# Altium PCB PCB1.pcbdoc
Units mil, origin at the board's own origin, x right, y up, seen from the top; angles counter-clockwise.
Board outline 3975 x 3427.1 mil, 2 copper layers (Top Layer, Bottom Layer), stack 62.2 mil thick; 7 components, 8 nets, 63 pads, 0 vias.
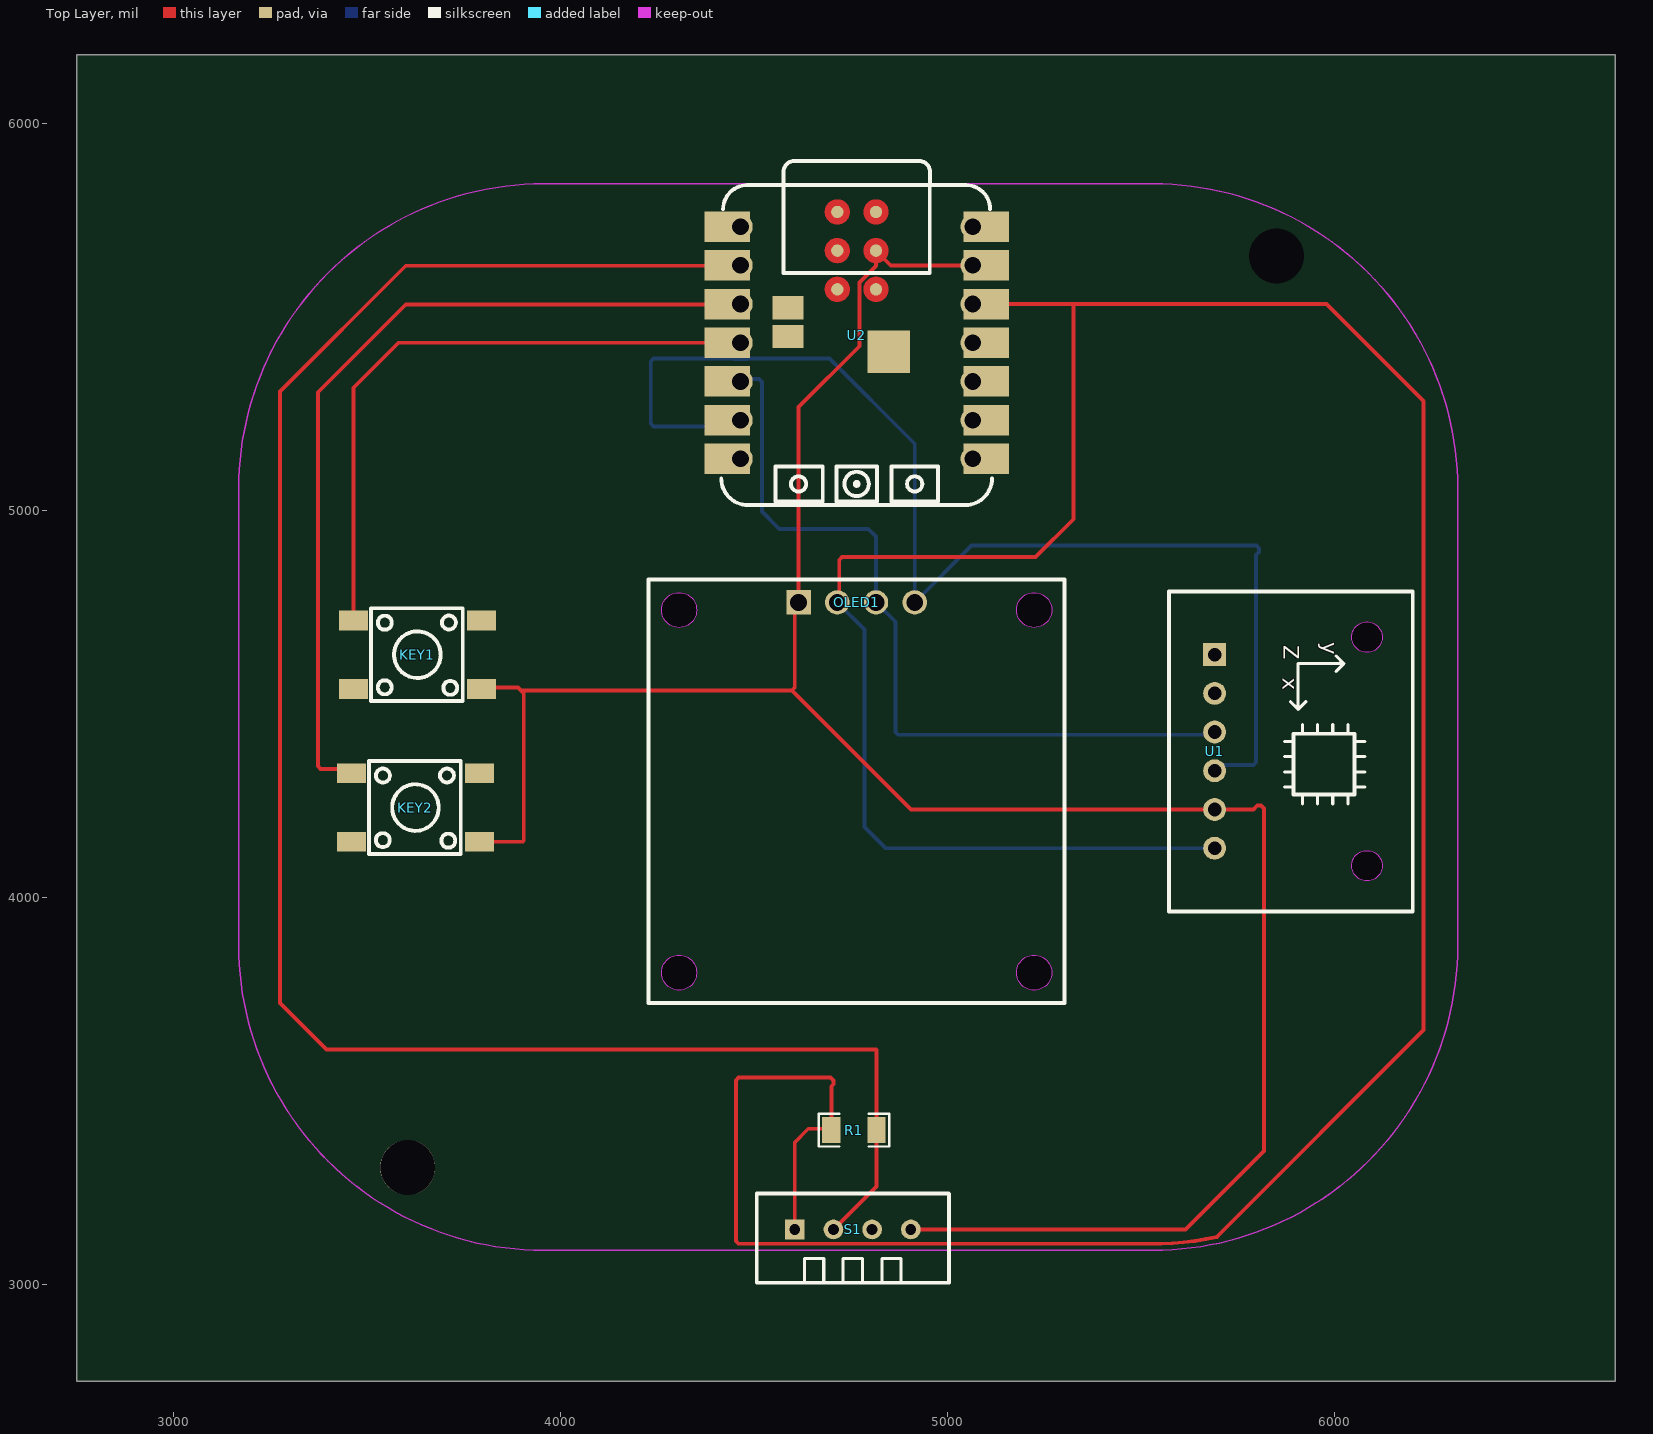
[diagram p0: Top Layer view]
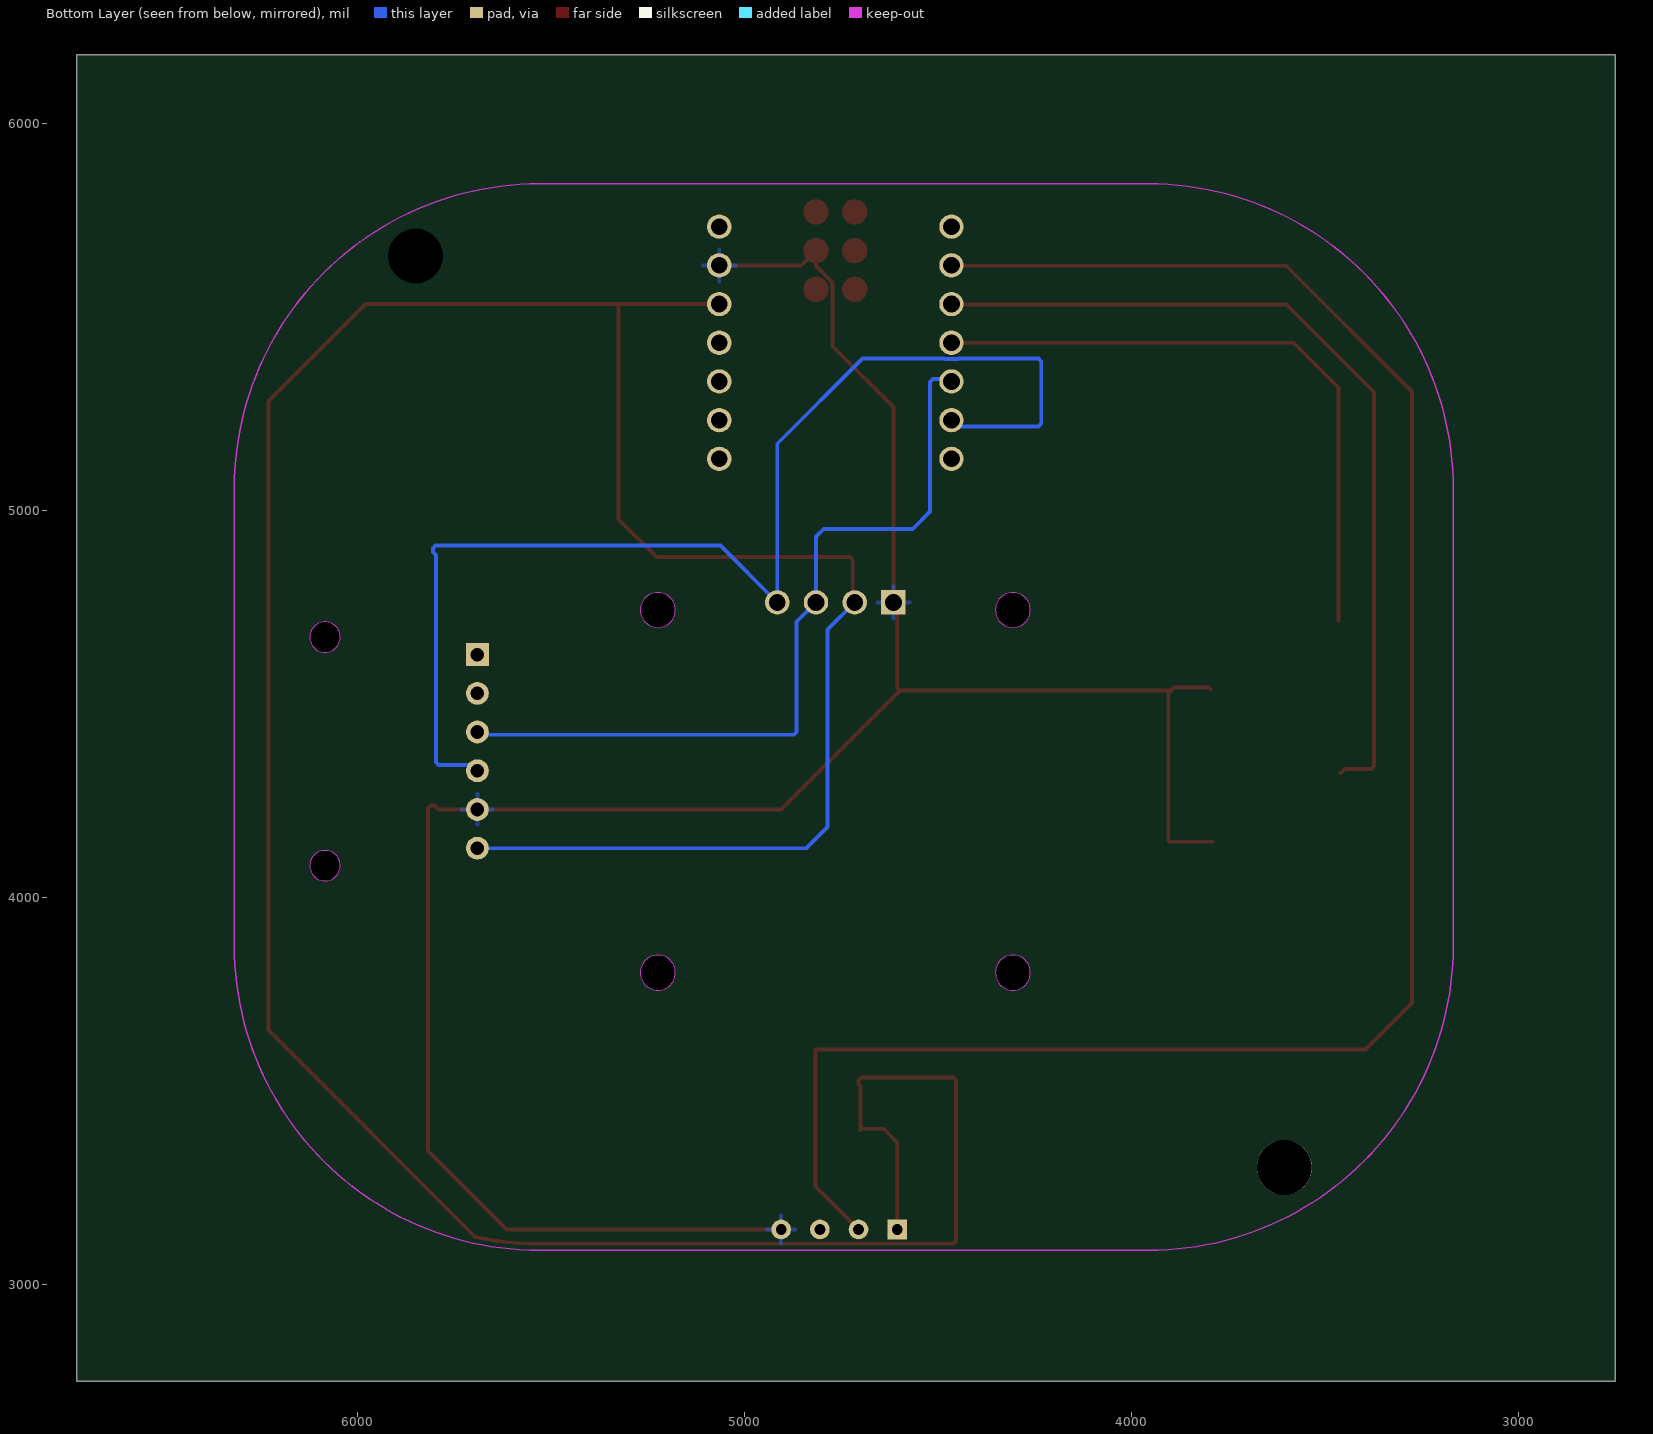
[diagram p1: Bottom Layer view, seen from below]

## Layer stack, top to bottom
Top Solder Mask Layer: solder mask 0.4, Dk 3.3
Top Layer: signal copper 1.4
Dielectric1: surface 59.4, FR4, Dk 4.5
Bottom Layer: signal copper 1.4
Bottom Solder Mask Layer: solder mask 0.4, Dk 3.3

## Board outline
6725,2750 2750,2750 2750,6177.1 6725,6177.1

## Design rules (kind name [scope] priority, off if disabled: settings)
BoardOutlineClearance copperThickness1oz [All] p0: genericclearance=10 ignorepadtopadclearanceinfootprint=FALSE except(0: Arc-SplitContinuation Track-SplitContinuation SMDPad-SplitContinuation THPad-SplitContinuation Via-SplitContinuation Fill-SplitContinuation Poly-SplitContinuation Region-SplitContinuation Text-SplitContinuation)
BoardOutlineClearance copperThickness2oz [All] p0: genericclearance=10 ignorepadtopadclearanceinfootprint=FALSE except(0: Arc-SplitContinuation Track-SplitContinuation SMDPad-SplitContinuation THPad-SplitContinuation Via-SplitContinuation Fill-SplitContinuation Poly-SplitContinuation Region-SplitContinuation Text-SplitContinuation)
BoardOutlineClearance otherClearance [All] p0: genericclearance=10 ignorepadtopadclearanceinfootprint=FALSE except(0: Arc-SplitContinuation Track-SplitContinuation SMDPad-SplitContinuation THPad-SplitContinuation Via-SplitContinuation Fill-SplitContinuation Poly-SplitContinuation Region-SplitContinuation Text-SplitContinuation)
Clearance copperThickness1oz [All] p1: gap=7 ignorepadtopadclearanceinfootprint=FALSE
Clearance copperThickness2oz [All] p1: gap=7 ignorepadtopadclearanceinfootprint=FALSE
Clearance otherClearance [All] p1: gap=7 ignorepadtopadclearanceinfootprint=FALSE
DiffPairsRouting differentialPair [All] p1: maxuncoupledlength=10 minlimit=6 maxlimit=Infinity mostfreqgap=6 toplayer_minwidth=5 toplayer_prefwidth=10 toplayer_maxwidth=100 bottomlayer_minwidth=5 bottomlayer_prefwidth=10 bottomlayer_maxwidth=100
PasteMaskExpansion pasteMaskExpansion [All] p1: expansion=0
PlaneConnect innerPlane [All] p1: planeconnectstyle=Relief reliefexpansion=20 reliefentries=4 reliefconductorwidth=10 reliefairgap=10
PolygonConnect copperRegion [All] p1: connectstyle=Relief reliefentries=4 reliefconductorwidth=10 polygonreliefangle="90 Angle" airgapwidth=10
RoutingVias viaSize [All] p1: viastyle="Through Hole" holewidth=12.0078 minholewidth=11.811 maxholewidth=248.0314 width=12.0078 minwidth=11.811 maxwidth=248.0314
SolderMaskExpansion solderMaskExpansion [IsVia] p1: useseparateexpansions=TRUE expansion=-1000 expansionbottom=-1000
SolderMaskExpansion solderMaskExpansion [All] p2: useseparateexpansions=TRUE expansion=2 expansionbottom=2
Width copperThickness1oz [All] p1: maxlimit=100 minlimit=5 preferedwidth=10
Width copperThickness2oz [All] p1: maxlimit=100 minlimit=8 preferedwidth=10

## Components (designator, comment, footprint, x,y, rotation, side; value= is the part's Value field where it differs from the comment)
KEY1 "BUTTON1" KEY-SMD_4P-L6.0-W6.0-P4.50-LS9.0 3630,4627.1 r0 top
KEY2 "BUTTON1" KEY-SMD_4P-L6.0-W6.0-P4.50-LS9.0 3625,4232.1 r0 top
OLED1 "MC096GW" OLED-TH_4P-L27.8-W27.3_MC096GW 4765,4762.1 r0 top
R1 "10kΩ" R1206 4758,3398.7 r0 top
S1 "DHT11" SENSOR-TH_DHT11-1 4755,3142.1 r0 top
U1 "MPU6050-TH" COMM-TH_MPU6050-TH 5690,4377.1 r270 top
U2 "XIAO ESP32C3" CONN-SMD_XIAO_ESP32C3 4765,5452.1 r0 top

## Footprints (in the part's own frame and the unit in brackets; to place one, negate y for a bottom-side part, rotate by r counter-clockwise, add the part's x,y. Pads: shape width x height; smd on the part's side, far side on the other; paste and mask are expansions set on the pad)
COMM-TH_MPU6050-TH [mil]
  rect 59.1x59.1 hole 35.4 paste+0 mask+2: 1(-250,0)
  round 59.1 hole 35.4 paste+0 mask+2: 2(-150,0) 3(-50,0) 4(50,0) 5(150,0) 6(250,0)
  Board Outline Layer lines w0.1: 296.6,354.4 302.1,354.9 307.4,356.3 312.5,358.3 317.3,361.1 321.6,364.4 325.4,368.4 328.6,372.8 331.2,377.7 333.1,382.9 334.2,388.2 334.6,393.7 334.2,399.2 333.1,404.6 331.2,409.7 328.6,414.6 325.4,419 321.6,423 317.3,426.3 312.5,429.1 307.4,431.1 302.1,432.5 296.6,433 291.1,432.9 285.7,431.9 280.5,430.2 275.6,427.8 271,424.7 266.9,421.1 263.4,416.8 260.5,412.2 258.2,407.2 256.7,401.9 256,396.4 256,391 256.7,385.5 258.2,380.2 260.5,375.2 263.4,370.6 266.9,366.4 271,362.7 275.6,359.6 280.5,357.2 285.7,355.5 291.1,354.5 296.6,354.4 ; -293.9,354.4 -288.5,354.9 -283.1,356.3 -278,358.3 -273.3,361.1 -269,364.4 -265.1,368.4 -261.9,372.8 -259.3,377.7 -257.5,382.9 -256.3,388.2 -255.9,393.7 -256.3,399.2 -257.5,404.6 -259.3,409.7 -261.9,414.6 -265.1,419 -269,423 -273.3,426.3 -278,429.1 -283.1,431.1 -288.5,432.5 -293.9,433 -299.4,432.9 -304.8,431.9 -310.1,430.2 -315,427.8 -319.5,424.7 -323.6,421.1 -327.2,416.8 -330.1,412.2 -332.3,407.2 -333.8,401.9 -334.6,396.4 -334.6,391 -333.8,385.5 -332.3,380.2 -330.1,375.2 -327.2,370.6 -323.6,366.4 -319.5,362.7 -315,359.6 -310.1,357.2 -304.8,355.5 -299.4,354.5 -293.9,354.4
  Board Outline Layer region: -255.9,393.7 -256.3,388.2 -257.5,382.9 -259.3,377.7 -261.9,372.8 -265.1,368.4 -269,364.4 -273.3,361.1 -278,358.3 -283.1,356.3 -288.5,354.9 -293.9,354.4 -299.4,354.5 -304.8,355.5 -310.1,357.2 -315,359.6 -319.5,362.7 -323.6,366.4 -327.2,370.6 -330.1,375.2 -332.3,380.2 -333.8,385.5 -334.6,391 -334.6,396.4 -333.8,401.9 -332.3,407.2 -330.1,412.2 -327.2,416.8 -323.6,421.1 -319.5,424.7 -315,427.8 -310.1,430.2 -304.8,431.9 -299.4,432.9 -293.9,433 -288.5,432.5 -283.1,431.1 -278,429.1 -273.3,426.3 -269,423 -265.1,419 -261.9,414.6 -259.3,409.7 -257.5,404.6 -256.3,399.2
  Board Outline Layer region: -255.9,393.7 -256.3,388.2 -257.5,382.9 -259.3,377.7 -261.9,372.8 -265.1,368.4 -269,364.4 -273.3,361.1 -278,358.3 -283.1,356.3 -288.5,354.9 -293.9,354.4 -299.4,354.5 -304.8,355.5 -310.1,357.2 -315,359.6 -319.5,362.7 -323.6,366.4 -327.2,370.6 -330.1,375.2 -332.3,380.2 -333.8,385.5 -334.6,391 -334.6,396.4 -333.8,401.9 -332.3,407.2 -330.1,412.2 -327.2,416.8 -323.6,421.1 -319.5,424.7 -315,427.8 -310.1,430.2 -304.8,431.9 -299.4,432.9 -293.9,433 -288.5,432.5 -283.1,431.1 -278,429.1 -273.3,426.3 -269,423 -265.1,419 -261.9,414.6 -259.3,409.7 -257.5,404.6 -256.3,399.2
  Board Outline Layer region: 334.6,393.7 334.2,388.2 333.1,382.9 331.2,377.7 328.6,372.8 325.4,368.4 321.6,364.4 317.3,361.1 312.5,358.3 307.4,356.3 302.1,354.9 296.6,354.4 291.1,354.5 285.7,355.5 280.5,357.2 275.6,359.6 271,362.7 266.9,366.4 263.4,370.6 260.5,375.2 258.2,380.2 256.7,385.5 256,391 256,396.4 256.7,401.9 258.2,407.2 260.5,412.2 263.4,416.8 266.9,421.1 271,424.7 275.6,427.8 280.5,430.2 285.7,431.9 291.1,432.9 296.6,433 302.1,432.5 307.4,431.1 312.5,429.1 317.3,426.3 321.6,423 325.4,419 328.6,414.6 331.2,409.7 333.1,404.6 334.2,399.2
  Board Outline Layer region: 334.6,393.7 334.2,388.2 333.1,382.9 331.2,377.7 328.6,372.8 325.4,368.4 321.6,364.4 317.3,361.1 312.5,358.3 307.4,356.3 302.1,354.9 296.6,354.4 291.1,354.5 285.7,355.5 280.5,357.2 275.6,359.6 271,362.7 266.9,366.4 263.4,370.6 260.5,375.2 258.2,380.2 256.7,385.5 256,391 256,396.4 256.7,401.9 258.2,407.2 260.5,412.2 263.4,416.8 266.9,421.1 271,424.7 275.6,427.8 280.5,430.2 285.7,431.9 291.1,432.9 296.6,433 302.1,432.5 307.4,431.1 312.5,429.1 317.3,426.3 321.6,423 325.4,419 328.6,414.6 331.2,409.7 333.1,404.6 334.2,399.2
  Multi-Layer board cut-out: -255.9,393.7 -256.3,388.2 -257.5,382.9 -259.3,377.7 -261.9,372.8 -265.1,368.4 -269,364.4 -273.3,361.1 -278,358.3 -283.1,356.3 -288.5,354.9 -293.9,354.4 -299.4,354.5 -304.8,355.5 -310.1,357.2 -315,359.6 -319.5,362.7 -323.6,366.4 -327.2,370.6 -330.1,375.2 -332.3,380.2 -333.8,385.5 -334.6,391 -334.6,396.4 -333.8,401.9 -332.3,407.2 -330.1,412.2 -327.2,416.8 -323.6,421.1 -319.5,424.7 -315,427.8 -310.1,430.2 -304.8,431.9 -299.4,432.9 -293.9,433 -288.5,432.5 -283.1,431.1 -278,429.1 -273.3,426.3 -269,423 -265.1,419 -261.9,414.6 -259.3,409.7 -257.5,404.6 -256.3,399.2
  Multi-Layer board cut-out: 334.6,393.7 334.2,388.2 333.1,382.9 331.2,377.7 328.6,372.8 325.4,368.4 321.6,364.4 317.3,361.1 312.5,358.3 307.4,356.3 302.1,354.9 296.6,354.4 291.1,354.5 285.7,355.5 280.5,357.2 275.6,359.6 271,362.7 266.9,366.4 263.4,370.6 260.5,375.2 258.2,380.2 256.7,385.5 256,391 256,396.4 256.7,401.9 258.2,407.2 260.5,412.2 263.4,416.8 266.9,421.1 271,424.7 275.6,427.8 280.5,430.2 285.7,431.9 291.1,432.9 296.6,433 302.1,432.5 307.4,431.1 312.5,429.1 317.3,426.3 321.6,423 325.4,419 328.6,414.6 331.2,409.7 333.1,404.6 334.2,399.2
  silkscreen extent -413,-118 413,512
CONN-SMD_XIAO_ESP32C3 [mil]
  rect 118.1x78.7 smd: 1(-334.6,281) 2(-334.6,181) 3(-334.6,81) 4(-334.6,-19) 5(-334.6,-119) 6(-334.6,-219) 7(-334.6,-319) 8(334.6,-319) 9(334.6,-219) 10(334.6,-119) 11(334.6,-19) 12(334.6,81) 13(334.6,181) 14(334.6,281)
  round 63 hole 43.3: 1(-300,281) 2(-300,181) 3(-300,81) 4(-300,-19) 5(-300,-119) 6(-300,-219) 7(-300,-319) 8(300,-319) 9(300,-219) 10(300,-119) 11(300,-19) 12(300,81) 13(300,181) 14(300,281)
  rect 80x60 smd: 15(-177.2,-3.2) 16(-177.2,71.6)
  rect 110.2x110.2 smd: 17(82.7,-42.6)
  round 32 smd: 18(50,119) 19(-50,119) 20(50,219) 21(-50,219) 22(50,319) 23(-50,319)
  Top Layer region: 204 vertices and 0 holes, not listed, extent -82,287 -18,351
  Top Layer region: 204 vertices and 0 holes, not listed, extent 18,287 82,351
  Top Layer region: 204 vertices and 0 holes, not listed, extent 18,187 82,251
  Top Layer region: 204 vertices and 0 holes, not listed, extent -82,187 -18,251
  Top Layer region: 204 vertices and 0 holes, not listed, extent 18,87 82,151
  Top Layer region: 204 vertices and 0 holes, not listed, extent -82,87 -18,151
  silkscreen extent -350,-438 350,451
KEY-SMD_4P-L6.0-W6.0-P4.50-LS9.0 [mil]
  rect 74.8x51.2 smd: 1(-165.3,88.6) 2(165.3,88.6) 3(-165.3,-88.5) 4(165.3,-88.5)
  silkscreen extent -120,-120 117,120
OLED-TH_4P-L27.8-W27.3_MC096GW [mil]
  rect 63x63 hole 43.3: 1(-150,0)
  round 63 hole 43.3: 2(-50,0) 3(50,0) 4(150,0)
  Board Outline Layer lines w0.1: -503.9,-956.7 -503.5,-962.6 -502.4,-968.4 -500.5,-974 -497.9,-979.3 -494.6,-984.2 -490.7,-988.7 -486.2,-992.6 -481.3,-995.9 -476,-998.5 -470.4,-1000.4 -464.6,-1001.5 -458.7,-1001.9 -452.8,-1001.5 -446.9,-1000.4 -441.3,-998.5 -436,-995.9 -431.1,-992.6 -426.6,-988.7 -422.7,-984.2 -419.4,-979.3 -416.8,-974 -414.9,-968.4 -413.8,-962.6 -413.4,-956.7 -413.8,-950.7 -414.9,-944.9 -416.8,-939.3 -419.4,-934 -422.7,-929.1 -426.6,-924.6 -431.1,-920.7 -436,-917.4 -441.3,-914.8 -446.9,-912.9 -452.8,-911.8 -458.7,-911.4 -464.6,-911.8 -470.4,-912.9 -476,-914.8 -481.3,-917.4 -486.2,-920.7 -490.7,-924.6 -494.6,-929.1 -497.9,-934 -500.5,-939.3 -502.4,-944.9 -503.5,-950.7 -503.9,-956.7 ; -503.9,-19.7 -503.5,-25.6 -502.4,-31.4 -500.5,-37 -497.9,-42.3 -494.6,-47.2 -490.7,-51.7 -486.2,-55.6 -481.3,-58.9 -476,-61.5 -470.4,-63.4 -464.6,-64.5 -458.7,-64.9 -452.8,-64.5 -446.9,-63.4 -441.3,-61.5 -436,-58.9 -431.1,-55.6 -426.6,-51.7 -422.7,-47.2 -419.4,-42.3 -416.8,-37 -414.9,-31.4 -413.8,-25.6 -413.4,-19.7 -413.8,-13.7 -414.9,-7.9 -416.8,-2.3 -419.4,3 -422.7,7.9 -426.6,12.4 -431.1,16.3 -436,19.6 -441.3,22.2 -446.9,24.1 -452.8,25.2 -458.7,25.6 -464.6,25.2 -470.4,24.1 -476,22.2 -481.3,19.6 -486.2,16.3 -490.7,12.4 -494.6,7.9 -497.9,3 -500.5,-2.3 -502.4,-7.9 -503.5,-13.7 -503.9,-19.7 ; 413.4,-956.7 413.8,-962.6 414.9,-968.4 416.8,-974 419.4,-979.3 422.7,-984.2 426.6,-988.7 431.1,-992.6 436,-995.9 441.3,-998.5 446.9,-1000.4 452.8,-1001.5 458.7,-1001.9 464.6,-1001.5 470.4,-1000.4 476,-998.5 481.3,-995.9 486.2,-992.6 490.7,-988.7 494.6,-984.2 497.9,-979.3 500.5,-974 502.4,-968.4 503.5,-962.6 503.9,-956.7 503.5,-950.7 502.4,-944.9 500.5,-939.3 497.9,-934 494.6,-929.1 490.7,-924.6 486.2,-920.7 481.3,-917.4 476,-914.8 470.4,-912.9 464.6,-911.8 458.7,-911.4 452.8,-911.8 446.9,-912.9 441.3,-914.8 436,-917.4 431.1,-920.7 426.6,-924.6 422.7,-929.1 419.4,-934 416.8,-939.3 414.9,-944.9 413.8,-950.7 413.4,-956.7 ; 413.4,-19.7 413.8,-25.6 414.9,-31.4 416.8,-37 419.4,-42.3 422.7,-47.2 426.6,-51.7 431.1,-55.6 436,-58.9 441.3,-61.5 446.9,-63.4 452.8,-64.5 458.7,-64.9 464.6,-64.5 470.4,-63.4 476,-61.5 481.3,-58.9 486.2,-55.6 490.7,-51.7 494.6,-47.2 497.9,-42.3 500.5,-37 502.4,-31.4 503.5,-25.6 503.9,-19.7 503.5,-13.7 502.4,-7.9 500.5,-2.3 497.9,3 494.6,7.9 490.7,12.4 486.2,16.3 481.3,19.6 476,22.2 470.4,24.1 464.6,25.2 458.7,25.6 452.8,25.2 446.9,24.1 441.3,22.2 436,19.6 431.1,16.3 426.6,12.4 422.7,7.9 419.4,3 416.8,-2.3 414.9,-7.9 413.8,-13.7 413.4,-19.7
  Board Outline Layer region: 503.9,-956.7 503.5,-962.6 502.4,-968.4 500.5,-974 497.9,-979.3 494.6,-984.2 490.7,-988.7 486.2,-992.6 481.3,-995.9 476,-998.5 470.4,-1000.4 464.6,-1001.5 458.7,-1001.9 452.8,-1001.5 446.9,-1000.4 441.3,-998.5 436,-995.9 431.1,-992.6 426.6,-988.7 422.7,-984.2 419.4,-979.3 416.8,-974 414.9,-968.4 413.8,-962.6 413.4,-956.7 413.8,-950.7 414.9,-944.9 416.8,-939.3 419.4,-934 422.7,-929.1 426.6,-924.6 431.1,-920.7 436,-917.4 441.3,-914.8 446.9,-912.9 452.8,-911.8 458.7,-911.4 464.6,-911.8 470.4,-912.9 476,-914.8 481.3,-917.4 486.2,-920.7 490.7,-924.6 494.6,-929.1 497.9,-934 500.5,-939.3 502.4,-944.9 503.5,-950.7
  Board Outline Layer region: 503.9,-956.7 503.5,-962.6 502.4,-968.4 500.5,-974 497.9,-979.3 494.6,-984.2 490.7,-988.7 486.2,-992.6 481.3,-995.9 476,-998.5 470.4,-1000.4 464.6,-1001.5 458.7,-1001.9 452.8,-1001.5 446.9,-1000.4 441.3,-998.5 436,-995.9 431.1,-992.6 426.6,-988.7 422.7,-984.2 419.4,-979.3 416.8,-974 414.9,-968.4 413.8,-962.6 413.4,-956.7 413.8,-950.7 414.9,-944.9 416.8,-939.3 419.4,-934 422.7,-929.1 426.6,-924.6 431.1,-920.7 436,-917.4 441.3,-914.8 446.9,-912.9 452.8,-911.8 458.7,-911.4 464.6,-911.8 470.4,-912.9 476,-914.8 481.3,-917.4 486.2,-920.7 490.7,-924.6 494.6,-929.1 497.9,-934 500.5,-939.3 502.4,-944.9 503.5,-950.7
  Board Outline Layer region: -413.4,-956.7 -413.8,-962.6 -414.9,-968.4 -416.8,-974 -419.4,-979.3 -422.7,-984.2 -426.6,-988.7 -431.1,-992.6 -436,-995.9 -441.3,-998.5 -446.9,-1000.4 -452.8,-1001.5 -458.7,-1001.9 -464.6,-1001.5 -470.4,-1000.4 -476,-998.5 -481.3,-995.9 -486.2,-992.6 -490.7,-988.7 -494.6,-984.2 -497.9,-979.3 -500.5,-974 -502.4,-968.4 -503.5,-962.6 -503.9,-956.7 -503.5,-950.7 -502.4,-944.9 -500.5,-939.3 -497.9,-934 -494.6,-929.1 -490.7,-924.6 -486.2,-920.7 -481.3,-917.4 -476,-914.8 -470.4,-912.9 -464.6,-911.8 -458.7,-911.4 -452.8,-911.8 -446.9,-912.9 -441.3,-914.8 -436,-917.4 -431.1,-920.7 -426.6,-924.6 -422.7,-929.1 -419.4,-934 -416.8,-939.3 -414.9,-944.9 -413.8,-950.7
  Board Outline Layer region: -413.4,-956.7 -413.8,-962.6 -414.9,-968.4 -416.8,-974 -419.4,-979.3 -422.7,-984.2 -426.6,-988.7 -431.1,-992.6 -436,-995.9 -441.3,-998.5 -446.9,-1000.4 -452.8,-1001.5 -458.7,-1001.9 -464.6,-1001.5 -470.4,-1000.4 -476,-998.5 -481.3,-995.9 -486.2,-992.6 -490.7,-988.7 -494.6,-984.2 -497.9,-979.3 -500.5,-974 -502.4,-968.4 -503.5,-962.6 -503.9,-956.7 -503.5,-950.7 -502.4,-944.9 -500.5,-939.3 -497.9,-934 -494.6,-929.1 -490.7,-924.6 -486.2,-920.7 -481.3,-917.4 -476,-914.8 -470.4,-912.9 -464.6,-911.8 -458.7,-911.4 -452.8,-911.8 -446.9,-912.9 -441.3,-914.8 -436,-917.4 -431.1,-920.7 -426.6,-924.6 -422.7,-929.1 -419.4,-934 -416.8,-939.3 -414.9,-944.9 -413.8,-950.7
  Board Outline Layer region: 503.9,-19.7 503.5,-25.6 502.4,-31.4 500.5,-37 497.9,-42.3 494.6,-47.2 490.7,-51.7 486.2,-55.6 481.3,-58.9 476,-61.5 470.4,-63.4 464.6,-64.5 458.7,-64.9 452.8,-64.5 446.9,-63.4 441.3,-61.5 436,-58.9 431.1,-55.6 426.6,-51.7 422.7,-47.2 419.4,-42.3 416.8,-37 414.9,-31.4 413.8,-25.6 413.4,-19.7 413.8,-13.7 414.9,-7.9 416.8,-2.3 419.4,3 422.7,7.9 426.6,12.4 431.1,16.3 436,19.6 441.3,22.2 446.9,24.1 452.8,25.2 458.7,25.6 464.6,25.2 470.4,24.1 476,22.2 481.3,19.6 486.2,16.3 490.7,12.4 494.6,7.9 497.9,3 500.5,-2.3 502.4,-7.9 503.5,-13.7
  Board Outline Layer region: 503.9,-19.7 503.5,-25.6 502.4,-31.4 500.5,-37 497.9,-42.3 494.6,-47.2 490.7,-51.7 486.2,-55.6 481.3,-58.9 476,-61.5 470.4,-63.4 464.6,-64.5 458.7,-64.9 452.8,-64.5 446.9,-63.4 441.3,-61.5 436,-58.9 431.1,-55.6 426.6,-51.7 422.7,-47.2 419.4,-42.3 416.8,-37 414.9,-31.4 413.8,-25.6 413.4,-19.7 413.8,-13.7 414.9,-7.9 416.8,-2.3 419.4,3 422.7,7.9 426.6,12.4 431.1,16.3 436,19.6 441.3,22.2 446.9,24.1 452.8,25.2 458.7,25.6 464.6,25.2 470.4,24.1 476,22.2 481.3,19.6 486.2,16.3 490.7,12.4 494.6,7.9 497.9,3 500.5,-2.3 502.4,-7.9 503.5,-13.7
  Board Outline Layer region: -413.4,-19.7 -413.8,-25.6 -414.9,-31.4 -416.8,-37 -419.4,-42.3 -422.7,-47.2 -426.6,-51.7 -431.1,-55.6 -436,-58.9 -441.3,-61.5 -446.9,-63.4 -452.8,-64.5 -458.7,-64.9 -464.6,-64.5 -470.4,-63.4 -476,-61.5 -481.3,-58.9 -486.2,-55.6 -490.7,-51.7 -494.6,-47.2 -497.9,-42.3 -500.5,-37 -502.4,-31.4 -503.5,-25.6 -503.9,-19.7 -503.5,-13.7 -502.4,-7.9 -500.5,-2.3 -497.9,3 -494.6,7.9 -490.7,12.4 -486.2,16.3 -481.3,19.6 -476,22.2 -470.4,24.1 -464.6,25.2 -458.7,25.6 -452.8,25.2 -446.9,24.1 -441.3,22.2 -436,19.6 -431.1,16.3 -426.6,12.4 -422.7,7.9 -419.4,3 -416.8,-2.3 -414.9,-7.9 -413.8,-13.7
  Board Outline Layer region: -413.4,-19.7 -413.8,-25.6 -414.9,-31.4 -416.8,-37 -419.4,-42.3 -422.7,-47.2 -426.6,-51.7 -431.1,-55.6 -436,-58.9 -441.3,-61.5 -446.9,-63.4 -452.8,-64.5 -458.7,-64.9 -464.6,-64.5 -470.4,-63.4 -476,-61.5 -481.3,-58.9 -486.2,-55.6 -490.7,-51.7 -494.6,-47.2 -497.9,-42.3 -500.5,-37 -502.4,-31.4 -503.5,-25.6 -503.9,-19.7 -503.5,-13.7 -502.4,-7.9 -500.5,-2.3 -497.9,3 -494.6,7.9 -490.7,12.4 -486.2,16.3 -481.3,19.6 -476,22.2 -470.4,24.1 -464.6,25.2 -458.7,25.6 -452.8,25.2 -446.9,24.1 -441.3,22.2 -436,19.6 -431.1,16.3 -426.6,12.4 -422.7,7.9 -419.4,3 -416.8,-2.3 -414.9,-7.9 -413.8,-13.7
  Multi-Layer board cut-out: 503.9,-956.7 503.5,-962.6 502.4,-968.4 500.5,-974 497.9,-979.3 494.6,-984.2 490.7,-988.7 486.2,-992.6 481.3,-995.9 476,-998.5 470.4,-1000.4 464.6,-1001.5 458.7,-1001.9 452.8,-1001.5 446.9,-1000.4 441.3,-998.5 436,-995.9 431.1,-992.6 426.6,-988.7 422.7,-984.2 419.4,-979.3 416.8,-974 414.9,-968.4 413.8,-962.6 413.4,-956.7 413.8,-950.7 414.9,-944.9 416.8,-939.3 419.4,-934 422.7,-929.1 426.6,-924.6 431.1,-920.7 436,-917.4 441.3,-914.8 446.9,-912.9 452.8,-911.8 458.7,-911.4 464.6,-911.8 470.4,-912.9 476,-914.8 481.3,-917.4 486.2,-920.7 490.7,-924.6 494.6,-929.1 497.9,-934 500.5,-939.3 502.4,-944.9 503.5,-950.7
  Multi-Layer board cut-out: -413.4,-956.7 -413.8,-962.6 -414.9,-968.4 -416.8,-974 -419.4,-979.3 -422.7,-984.2 -426.6,-988.7 -431.1,-992.6 -436,-995.9 -441.3,-998.5 -446.9,-1000.4 -452.8,-1001.5 -458.7,-1001.9 -464.6,-1001.5 -470.4,-1000.4 -476,-998.5 -481.3,-995.9 -486.2,-992.6 -490.7,-988.7 -494.6,-984.2 -497.9,-979.3 -500.5,-974 -502.4,-968.4 -503.5,-962.6 -503.9,-956.7 -503.5,-950.7 -502.4,-944.9 -500.5,-939.3 -497.9,-934 -494.6,-929.1 -490.7,-924.6 -486.2,-920.7 -481.3,-917.4 -476,-914.8 -470.4,-912.9 -464.6,-911.8 -458.7,-911.4 -452.8,-911.8 -446.9,-912.9 -441.3,-914.8 -436,-917.4 -431.1,-920.7 -426.6,-924.6 -422.7,-929.1 -419.4,-934 -416.8,-939.3 -414.9,-944.9 -413.8,-950.7
  Multi-Layer board cut-out: 503.9,-19.7 503.5,-25.6 502.4,-31.4 500.5,-37 497.9,-42.3 494.6,-47.2 490.7,-51.7 486.2,-55.6 481.3,-58.9 476,-61.5 470.4,-63.4 464.6,-64.5 458.7,-64.9 452.8,-64.5 446.9,-63.4 441.3,-61.5 436,-58.9 431.1,-55.6 426.6,-51.7 422.7,-47.2 419.4,-42.3 416.8,-37 414.9,-31.4 413.8,-25.6 413.4,-19.7 413.8,-13.7 414.9,-7.9 416.8,-2.3 419.4,3 422.7,7.9 426.6,12.4 431.1,16.3 436,19.6 441.3,22.2 446.9,24.1 452.8,25.2 458.7,25.6 464.6,25.2 470.4,24.1 476,22.2 481.3,19.6 486.2,16.3 490.7,12.4 494.6,7.9 497.9,3 500.5,-2.3 502.4,-7.9 503.5,-13.7
  Multi-Layer board cut-out: -413.4,-19.7 -413.8,-25.6 -414.9,-31.4 -416.8,-37 -419.4,-42.3 -422.7,-47.2 -426.6,-51.7 -431.1,-55.6 -436,-58.9 -441.3,-61.5 -446.9,-63.4 -452.8,-64.5 -458.7,-64.9 -464.6,-64.5 -470.4,-63.4 -476,-61.5 -481.3,-58.9 -486.2,-55.6 -490.7,-51.7 -494.6,-47.2 -497.9,-42.3 -500.5,-37 -502.4,-31.4 -503.5,-25.6 -503.9,-19.7 -503.5,-13.7 -502.4,-7.9 -500.5,-2.3 -497.9,3 -494.6,7.9 -490.7,12.4 -486.2,16.3 -481.3,19.6 -476,22.2 -470.4,24.1 -464.6,25.2 -458.7,25.6 -452.8,25.2 -446.9,24.1 -441.3,22.2 -436,19.6 -431.1,16.3 -426.6,12.4 -422.7,7.9 -419.4,3 -416.8,-2.3 -414.9,-7.9 -413.8,-13.7
  silkscreen extent -537,-1035 537,59
R1206 [mil]
  rect 47.5x67 smd paste-3937 mask+2: 1(-58.2,0) 2(58.3,0)
  silkscreen extent -91,-42 91,42
SENSOR-TH_DHT11-1 [mil]
  rect 51x51 hole 28: 1(-150,0)
  round 51 hole 28: 2(-50,0) 3(50,0) 4(150,0)
  silkscreen extent -248,-138 248,92

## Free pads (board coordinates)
  round 60 hole 141.7 unplated: 2(5850,5657.1)
  round 141.7 hole 141.7 unplated: 4(3605,3302.1)

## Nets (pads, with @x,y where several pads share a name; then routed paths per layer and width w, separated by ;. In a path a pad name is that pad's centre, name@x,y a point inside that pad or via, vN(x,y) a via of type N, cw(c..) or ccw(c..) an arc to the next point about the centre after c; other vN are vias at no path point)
3V3: OLED1.2 R1.1 S1.1 U1.6 U2.12 | length 8854.8
  Top Layer w10: S1.1 4605,3367.1 4640,3402.1 4696.4,3402.1 R1.1 4699.8,3512 4705,3517.1 4705,3527.1 4697.9,3534.2 4460,3534.2 4452.9,3527.1 4452.9,3112.1 4460,3105.1 5551.7,3105.1 ; OLED1.2 4720,4767.1 4720,4872.1 4727.1,4879.2 5227.1,4879.2 5325,4977.1 5325,5533 5325.1,5533.1 ; U2.12@5099.6,5533.1 5325.1,5533.1 ; 5552.12,3105.1 ccw(c5530.6,3875.4) 5696.08,3122.78 ; 5695.5,3122.6 6230,3657.1 6230,5282.1 5979,5533.1 5325.1,5533.1
  Bottom Layer w10: OLED1.2 4785,4692.1 4785,4182.1 4840,4127.1 U1.6
5V: U2.14
DHT11: R1.2 S1.2 U2.2 | length 4971.8
  Top Layer w10: U2.2@4430.4,5633.1 4429.4,5632.1 3600,5632.1 3275,5307.1 3275,3727.1 3395,3607.1 4815,3607.1 4816.3,3605.9 R1.2 4816.3,3253.4 S1.2
GND: KEY1.4 KEY2.4 OLED1.1 S1.4 U1.5 U2.13 U2.20 | length 6041.4
  Top Layer w10: KEY2.4 3901.4,4143.6 3905,4147.1 3905,4527.1 3897.5,4534.7 ; KEY1.4 3798.9,4542.1 3890,4542.1 3897.5,4534.7 ; S1.4 5615,3142.1 5817.1,3344.2 5817.1,4230.1 5810,4237.1 5800,4237.1 5790,4227.1 U1.5 4905.1,4227.1 4597.5,4534.7 ; U2.13@5065,5633.1 4853,5633.1 U2.20 4815,5631.9 4772,5588.9 4772,5424.2 4615,5267.1 OLED1.1 4605,4752.1 4605,4542.1 4597.5,4534.7 ; 3897.5,4534.7 4597.5,4534.7
GPIO2: KEY2.1 U2.3 | length 2246.8
  Top Layer w10: KEY2.1 3448.2,4332.1 3380,4332.1 3372.9,4339.2 3372.9,5305.1 3600,5532.1 4464,5532.1 U2.3@4465,5533.1
GPIO3: KEY1.1 U2.4 | length 1649.6
  Top Layer w10: KEY1.1 3464.7,5316.8 3581,5433.1 U2.4@4465,5433.1
SCL: OLED1.3 U1.3 U2.5 | length 2073.8
  Bottom Layer w10: U2.5@4465,5333.1 4471.1,5339.2 4512.9,5339.2 4520,5332.1 4520,4997.1 4565,4952.1 4795,4952.1 4815,4932.1 OLED1.3 4865,4712.1 4865,4427.1 4872.1,4420.1 5682.9,4420.1 U1.3
SDA: OLED1.4 U1.4 U2.6 | length 3216.1
  Bottom Layer w10: U2.6@4465,5233.1 4449,5217.1 4240,5217.1 4232.9,5224.2 4232.9,5385.1 4240,5392.1 4445.9,5392.1 4447.4,5390.7 4482.6,5390.7 4484.1,5392.1 4695,5392.1 4915,5172.1 OLED1.4 5062.1,4909.2 5797.9,4909.2 5805,4902.1 5805,4892.1 5797.1,4884.2 5797.1,4349.2 5790,4342.1 5705,4342.1 U1.4
pads on no net: KEY1.2 KEY1.3 KEY2.2 KEY2.3 S1.3 U1.1 U1.2 U2.1 U2.7 U2.8 U2.9 U2.10 U2.11 U2.15 U2.16 U2.17 U2.18 U2.19 U2.21 U2.22 U2.23

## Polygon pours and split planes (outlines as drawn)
GND on Bottom Layer (solid, remove dead copper, pour order 0): 3000,5927.1 3000,3032.1 6475,3032.1 6475,5927.1

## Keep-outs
Board Outline Layer:
  lines w3.9: 3168.4,3875.4 3168.4,5056.5 3168.8,5081.2 3170,5105.9 3171.9,5130.6 3174.6,5155.2 3178.1,5179.7 3182.4,5204 3187.4,5228.2 3193.2,5252.3 3199.7,5276.2 3207,5299.8 3215,5323.2 3223.7,5346.3 3233.2,5369.2 3243.4,5391.7 3254.2,5413.9 3265.8,5435.8 3278.1,5457.3 3291,5478.4 3304.6,5499.1 3318.8,5519.3 3333.7,5539.1 3349.1,5558.4 3365.2,5577.2 3381.8,5595.5 3399,5613.3 3416.8,5630.5 3435.1,5647.1 3453.9,5663.2 3473.2,5678.6 3493,5693.5 3513.2,5707.7 3533.9,5721.3 3555,5734.2 3576.5,5746.5 3598.4,5758.1 3620.6,5768.9 3643.1,5779.1 3666,5788.6 3689.1,5797.3 3712.5,5805.3 3736.1,5812.6 3760,5819.1 3784.1,5824.9 3808.3,5829.9 3832.6,5834.2 3857.1,5837.7 3881.7,5840.4 3906.4,5842.3 3931.1,5843.5 3955.8,5843.9 5530.6,5843.9 5555.4,5843.5 5580.1,5842.3 5604.7,5840.4 5629.3,5837.7 5653.8,5834.2 5678.2,5829.9 5702.4,5824.9 5726.4,5819.1 5750.3,5812.6 5773.9,5805.3 5797.3,5797.3 5820.5,5788.6 5843.3,5779.1 5865.9,5768.9 5888.1,5758.1 5910,5746.5 5931.4,5734.2 5952.5,5721.3 5973.2,5707.7 5993.4,5693.5 6013.2,5678.6 6032.5,5663.2 6051.3,5647.1 6069.6,5630.5 6087.4,5613.3 6104.6,5595.5 6121.3,5577.2 6137.3,5558.4 6152.8,5539.1 6167.6,5519.3 6181.9,5499.1 6195.5,5478.4 6208.4,5457.3 6220.6,5435.8 6232.2,5413.9 6243.1,5391.7 6253.3,5369.2 6262.7,5346.3 6271.5,5323.2 6279.5,5299.8 6286.8,5276.2 6293.3,5252.3 6299.1,5228.2 6304.1,5204 6308.3,5179.7 6311.8,5155.2 6314.5,5130.6 6316.5,5105.9 6317.6,5081.2 6318,5056.5 6318,3875.4 6317.6,3850.6 6316.5,3825.9 6314.5,3801.3 6311.8,3776.7 6308.3,3752.2 6304.1,3727.8 6299.1,3703.6 6293.3,3679.6 6286.8,3655.7 6279.5,3632.1 6271.5,3608.6 6262.7,3585.5 6253.3,3562.7 6243.1,3540.1 6232.2,3517.9 6220.6,3496 6208.4,3474.6 6195.5,3453.5 6181.9,3432.8 6167.6,3412.5 6152.8,3392.8 6137.3,3373.5 6121.3,3354.7 6104.6,3336.4 6087.4,3318.6 6069.6,3301.4 6051.3,3284.7 6032.5,3268.7 6013.2,3253.2 5993.4,3238.4 5973.2,3224.1 5952.5,3210.5 5931.4,3197.6 5910,3185.4 5888.1,3173.8 5865.9,3162.9 5843.3,3152.7 5820.5,3143.3 5797.3,3134.5 5773.9,3126.5 5750.3,3119.2 5726.4,3112.7 5702.4,3106.9 5678.2,3101.9 5653.8,3097.7 5629.3,3094.2 5604.7,3091.5 5580.1,3089.5 5555.4,3088.4 5530.6,3088 3955.8,3088 3931.1,3088.4 3906.4,3089.5 3881.7,3091.5 3857.1,3094.2 3832.6,3097.7 3808.3,3101.9 3784.1,3106.9 3760,3112.7 3736.1,3119.2 3712.5,3126.5 3689.1,3134.5 3666,3143.3 3643.1,3152.7 3620.6,3162.9 3598.4,3173.8 3576.5,3185.4 3555,3197.6 3533.9,3210.5 3513.2,3224.1 3493,3238.4 3473.2,3253.2 3453.9,3268.7 3435.1,3284.7 3416.8,3301.4 3399,3318.6 3381.8,3336.4 3365.2,3354.7 3349.1,3373.5 3333.7,3392.8 3318.8,3412.5 3304.6,3432.8 3291,3453.5 3278.1,3474.6 3265.8,3496 3254.2,3517.9 3243.4,3540.1 3233.2,3562.7 3223.7,3585.5 3215,3608.6 3207,3632.1 3199.7,3655.7 3193.2,3679.6 3187.4,3703.6 3182.4,3727.8 3178.1,3752.2 3174.6,3776.7 3171.9,3801.3 3170,3825.9 3168.8,3850.6 3168.4,3875.4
